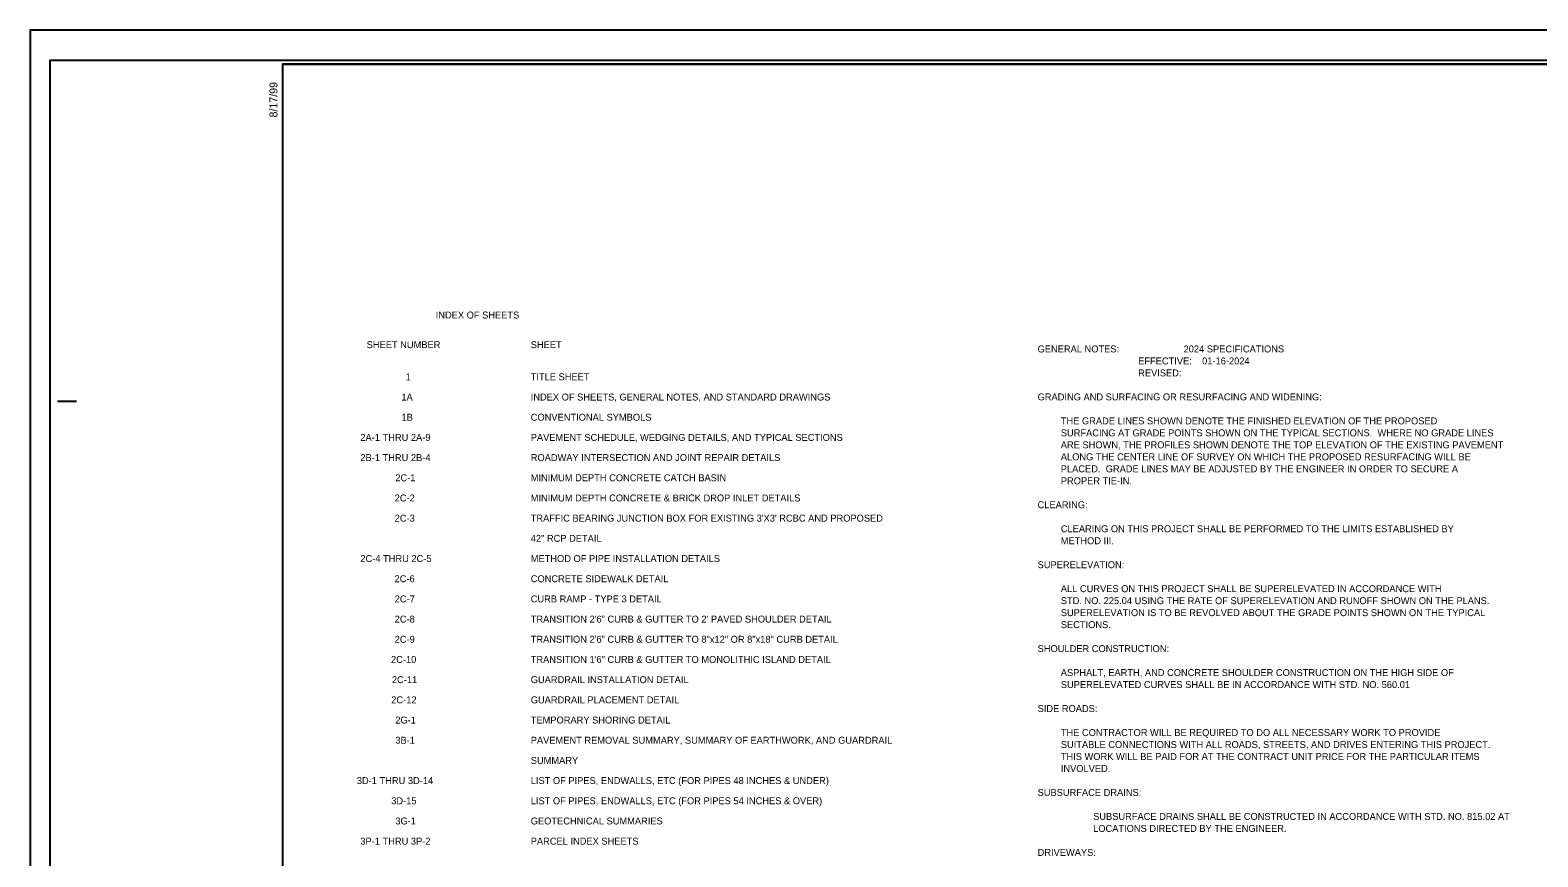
# Model space of a CAD drawing. Extents: x 1877070 to 1879304, y 464355 to 465670.
# Drawn here: x 1877070 to 1878265, y 465014 to 465670 of the extents above; entities that cross this region are included whole.
import ezdxf

# ---------------------------------------------------------------- set-up
doc = ezdxf.new("R2010")
doc.units = 0
for name, color, linetype in [('Prop AutoTurn Projected Path', 7, 'Continuous'), ('Prop EOT', 7, 'Continuous'), ('Prop Horizontal Alignment', 7, 'Continuous'), ('Prop Lane Lines', 7, 'Continuous'), ('Scratch_Level_0', 7, 'Continuous')]:
    doc.layers.add(name, color=color, linetype=linetype)

msp = doc.modelspace()

# ---------------------------------------------------------------- linework, layer by layer
at = {"layer": 'Prop AutoTurn Projected Path'}
msp.add_lwpolyline([(1877070, 464355.1), (1879090.8, 464355.1), (1879090.8, 465669.5), (1877070, 465669.5)], close=True, dxfattribs=at)
at = {"layer": 'Prop EOT'}
msp.add_line((1877269.8, 465642.5), (1879070.4, 465642.5), dxfattribs=at)
at = {"layer": 'Prop Lane Lines'}
msp.add_lwpolyline([(1877085.6, 464379.1), (1879085.4, 464379.1), (1879085.4, 465645.5), (1877085.6, 465645.5)], close=True, dxfattribs=at)
at = {"layer": 'Scratch_Level_0'}
for p, q in [((1877269.8, 465642.5), (1877269.8, 465642.5)), ((1877091.6, 465375.4), (1877106.6, 465375.4))]:
    msp.add_line(p, q, dxfattribs=at)
msp.add_lwpolyline([(1879070.4, 465642.5), (1877269.8, 465642.5), (1877269.8, 464382.1), (1879070.4, 464382.1)], close=True, dxfattribs=at)

# ---------------------------------------------------------------- texts
at = {"layer": 'Prop Horizontal Alignment'}
for s, p in [('INDEX OF SHEETS ', (1877391.3, 465441)), ('SHEET NUMBER', (1877336.6, 465417.5)), ('SHEET   ', (1877466.6, 465417.5)), ('GENERAL NOTES:                         2024 SPECIFICATIONS', (1877868.2, 465414.1)), ('                                       EFFECTIVE:    01-16-2024', (1877868.2, 465404.6)), ('1', (1877367.5, 465392)), ('TITLE SHEET', (1877466.6, 465392)), ('                                       REVISED:      ', (1877868.2, 465395.1)), ('1A', (1877364.1, 465376)), ('INDEX OF SHEETS, GENERAL NOTES, AND STANDARD DRAWINGS', (1877466.6, 465376)), ('GRADING AND SURFACING OR RESURFACING AND WIDENING:  ', (1877868.2, 465376.1)), ('1B', (1877364.2, 465360)), ('CONVENTIONAL SYMBOLS', (1877466.6, 465360)), ('         THE GRADE LINES SHOWN DENOTE THE FINISHED ELEVATION OF THE PROPOSED ', (1877868.2, 465357.1)), ('2A-1 THRU 2A-9', (1877331.6, 465344)), ('PAVEMENT SCHEDULE, WEDGING DETAILS, AND TYPICAL SECTIONS', (1877466.6, 465344)), ('         SURFACING AT GRADE POINTS SHOWN ON THE TYPICAL SECTIONS.  WHERE NO GRADE LINES ', (1877868.2, 465347.6)), ('         ARE SHOWN, THE PROFILES SHOWN DENOTE THE TOP ELEVATION OF THE EXISTING PAVEMENT ', (1877868.2, 465338.1)), ('2B-1 THRU 2B-4', (1877331.6, 465328)), ('ROADWAY INTERSECTION AND JOINT REPAIR DETAILS', (1877466.6, 465328)), ('         ALONG THE CENTER LINE OF SURVEY ON WHICH THE PROPOSED RESURFACING WILL BE ', (1877868.2, 465328.6)), ('2C-1 ', (1877359.3, 465312)), ('MINIMUM DEPTH CONCRETE CATCH BASIN', (1877466.6, 465312)), ('         PLACED.  GRADE LINES MAY BE ADJUSTED BY THE ENGINEER IN ORDER TO SECURE A ', (1877868.2, 465319.1)), ('         PROPER TIE-IN.  ', (1877868.2, 465309.6)), ('2C-2', (1877358.8, 465296)), ('MINIMUM DEPTH CONCRETE & BRICK DROP INLET DETAILS', (1877466.6, 465296)), ('CLEARING:  ', (1877868.2, 465290.6)), ('2C-3', (1877358.8, 465280)), ("TRAFFIC BEARING JUNCTION BOX FOR EXISTING 3'X3' RCBC AND PROPOSED ", (1877466.6, 465280)), ('42" RCP DETAIL', (1877466.6, 465264)), ('         CLEARING ON THIS PROJECT SHALL BE PERFORMED TO THE LIMITS ESTABLISHED BY ', (1877868.2, 465271.6)), ('         METHOD III.', (1877868.2, 465262.1)), ('2C-4 THRU 2C-5', (1877331.6, 465248)), ('METHOD OF PIPE INSTALLATION DETAILS', (1877466.6, 465248)), ('SUPERELEVATION:  ', (1877868.2, 465243.1)), ('2C-6', (1877358.7, 465232)), ('CONCRETE SIDEWALK DETAIL', (1877466.6, 465232)), ('         ALL CURVES ON THIS PROJECT SHALL BE SUPERELEVATED IN ACCORDANCE WITH', (1877868.2, 465224.1)), ('2C-7', (1877358.8, 465216)), ('CURB RAMP - TYPE 3 DETAIL', (1877466.6, 465216)), ('         STD. NO. 225.04 USING THE RATE OF SUPERELEVATION AND RUNOFF SHOWN ON THE PLANS.', (1877868.2, 465214.6)), ('2C-8', (1877358.8, 465200)), ('TRANSITION 2\'6" CURB & GUTTER TO 2\' PAVED SHOULDER DETAIL', (1877466.6, 465200)), ('         SUPERELEVATION IS TO BE REVOLVED ABOUT THE GRADE POINTS SHOWN ON THE TYPICAL ', (1877868.2, 465205.1)), ('         SECTIONS.  ', (1877868.2, 465195.6)), ('2C-9', (1877358.8, 465184)), ('TRANSITION 2\'6" CURB & GUTTER TO 8"x12" OR 8"x18" CURB DETAIL', (1877466.6, 465184)), ('SHOULDER CONSTRUCTION:  ', (1877868.2, 465176.6)), ('2C-10', (1877355.9, 465168)), ('TRANSITION 1\'6" CURB & GUTTER TO MONOLITHIC ISLAND DETAIL', (1877466.6, 465168)), ('         ASPHALT, EARTH, AND CONCRETE SHOULDER CONSTRUCTION ON THE HIGH SIDE OF', (1877868.2, 465157.6)), ('2C-11', (1877356.6, 465152)), ('GUARDRAIL INSTALLATION DETAIL', (1877466.6, 465152)), ('         SUPERELEVATED CURVES SHALL BE IN ACCORDANCE WITH STD. NO. 560.01', (1877868.2, 465148.1)), ('2C-12', (1877356.1, 465136)), ('GUARDRAIL PLACEMENT DETAIL', (1877466.6, 465136)), ('SIDE ROADS:  ', (1877868.2, 465129.1)), ('2G-1', (1877359.3, 465120)), ('TEMPORARY SHORING DETAIL', (1877466.6, 465120)), ('         THE CONTRACTOR WILL BE REQUIRED TO DO ALL NECESSARY WORK TO PROVIDE ', (1877868.2, 465110.1)), ('3B-1', (1877359.3, 465104)), ('PAVEMENT REMOVAL SUMMARY, SUMMARY OF EARTHWORK, AND GUARDRAIL ', (1877466.6, 465104)), ('         SUITABLE CONNECTIONS WITH ALL ROADS, STREETS, AND DRIVES ENTERING THIS PROJECT.  ', (1877868.2, 465100.6)), ('SUMMARY', (1877466.6, 465088)), ('         THIS WORK WILL BE PAID FOR AT THE CONTRACT UNIT PRICE FOR THE PARTICULAR ITEMS ', (1877868.2, 465091.1)), ('         INVOLVED.  ', (1877868.2, 465081.6)), ('3D-1 THRU 3D-14', (1877328.8, 465072)), ('LIST OF PIPES, ENDWALLS, ETC (FOR PIPES 48 INCHES & UNDER)', (1877466.6, 465072)), ('SUBSURFACE DRAINS:  ', (1877868.2, 465062.6)), ('3D-15', (1877356.1, 465056)), ('LIST OF PIPES, ENDWALLS, ETC (FOR PIPES 54 INCHES & OVER)', (1877466.6, 465056)), ('3G-1', (1877359.3, 465040)), ('GEOTECHNICAL SUMMARIES', (1877466.6, 465040)), ('SUBSURFACE DRAINS SHALL BE CONSTRUCTED IN ACCORDANCE WITH STD. NO. 815.02 AT', (1877912.2, 465043.6)), ('LOCATIONS DIRECTED BY THE ENGINEER.', (1877912.2, 465034.1)), ('3P-1 THRU 3P-2', (1877331.6, 465024)), ('PARCEL INDEX SHEETS', (1877466.6, 465024)), ('DRIVEWAYS:  ', (1877868.2, 465015.1))]:
    msp.add_text(s, height=5.5, dxfattribs=at).set_placement(p)
at = {"layer": 'Scratch_Level_0'}
msp.add_text('8/17/99', height=6.3, rotation=90, dxfattribs=at).set_placement((1877265.9, 465600.3))

doc.saveas('drawing.dxf')
